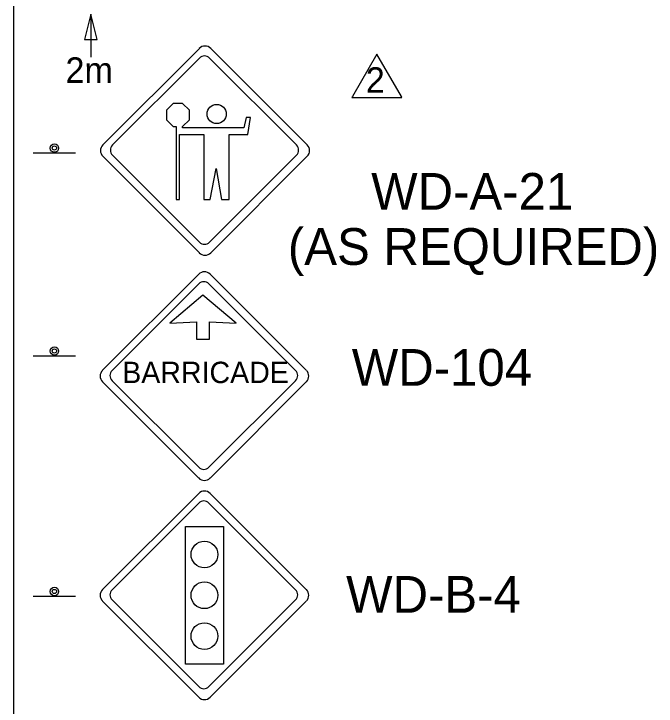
# Model space of a CAD drawing. Extents: x 2170 to 2386, y 134 to 413.
# Drawn here: x 2234.19 to 2270.72, y 251.29 to 290.65 of the extents above; entities that cross this region are included whole.
import ezdxf

# ---------------------------------------------------------------- set-up
doc = ezdxf.new("R2010")
doc.units = 0
for name, color, linetype in [('Level 1', 7, 'Continuous'), ('Level 10', 7, 'Continuous'), ('Level 44', 7, 'Continuous'), ('Level 60', 7, 'Continuous')]:
    doc.layers.add(name, color=color, linetype=linetype)

msp = doc.modelspace()

# ---------------------------------------------------------------- linework, layer by layer
at = {"layer": 'Level 1'}
for p, q in [((2243.249, 285.56), (2242.865, 285.176)), ((2243.791, 285.56), (2243.249, 285.56)), ((2244.175, 285.176), (2243.791, 285.56)), ((2242.865, 285.176), (2242.865, 284.634)), ((2244.175, 284.634), (2244.175, 285.176)), ((2242.865, 284.634), (2243.249, 284.25)), ((2243.791, 284.25), (2244.175, 284.634)), ((2247.407, 284.763), (2247.268, 284.18)), ((2247.651, 284.763), (2247.407, 284.763)), ((2247.492, 283.789), (2247.651, 284.763)), ((2243.249, 284.25), (2243.423, 284.25)), ((2243.423, 284.25), (2243.423, 280.097)), ((2243.791, 284.18), (2243.791, 284.25)), ((2247.268, 284.18), (2243.791, 284.18)), ((2243.613, 280.097), (2243.613, 283.789)), ((2243.613, 283.789), (2244.995, 283.789)), ((2244.995, 283.789), (2244.995, 280.097)), ((2246.445, 280.097), (2246.445, 283.789)), ((2246.445, 283.789), (2247.492, 283.789)), ((2245.362, 280.097), (2245.69, 281.866)), ((2245.69, 281.866), (2245.998, 280.097)), ((2243.423, 280.097), (2243.613, 280.097)), ((2244.995, 280.097), (2245.362, 280.097)), ((2245.998, 280.097), (2246.445, 280.097)), ((2243.949, 261.504), (2246.109, 261.504)), ((2243.949, 253.671), (2243.949, 261.504)), ((2243.949, 253.678), (2243.949, 261.504)), ((2246.109, 261.504), (2246.109, 253.678)), ((2246.109, 253.678), (2243.949, 253.678)), ((2243.949, 253.678), (2243.949, 253.671))]:
    msp.add_line(p, q, dxfattribs=at)
msp.add_circle((2245.725, 284.958), 0.544, dxfattribs=at)
at = {"layer": 'Level 10'}
for p, q in [((2234.191, 178.244), (2234.191, 321.298)), ((2238.57, 290.645), (2238.57, 288.196))]:
    msp.add_line(p, q, dxfattribs=at)
msp.add_lwpolyline([(2238.933, 289.194), (2238.57, 290.645), (2238.207, 289.194)], close=True, dxfattribs=at)
at = {"layer": 'Level 44'}
for p, q in [((2244.741, 288.689), (2239.247, 283.203)), ((2250.875, 283.203), (2245.39, 288.689)), ((2239.797, 283.199), (2244.741, 288.136)), ((2245.325, 288.136), (2250.263, 283.199)), ((2235.294, 282.754), (2237.69, 282.754)), ((2239.247, 282.552), (2244.741, 277.061)), ((2239.252, 282.552), (2239.247, 282.552)), ((2244.741, 277.672), (2239.797, 282.612)), ((2250.263, 282.612), (2245.325, 277.672)), ((2245.39, 277.061), (2250.875, 282.552)), ((2244.707, 275.853), (2239.229, 270.384)), ((2250.823, 270.384), (2245.354, 275.853)), ((2239.778, 270.379), (2244.707, 275.302)), ((2245.289, 275.302), (2250.213, 270.379)), ((2244.948, 274.656), (2243.066, 273.07)), ((2246.83, 273.07), (2244.948, 274.656)), ((2243.066, 273.07), (2244.571, 273.15)), ((2244.571, 273.15), (2244.571, 272.146)), ((2245.325, 272.146), (2245.325, 273.15)), ((2245.325, 273.15), (2246.83, 273.07)), ((2244.571, 272.146), (2245.32, 272.146)), ((2235.294, 271.214), (2237.69, 271.214)), ((2239.229, 269.734), (2244.707, 264.259)), ((2239.234, 269.734), (2239.229, 269.734)), ((2244.707, 264.868), (2239.778, 269.795)), ((2250.213, 269.795), (2245.289, 264.868)), ((2245.354, 264.259), (2250.823, 269.734)), ((2244.707, 263.385), (2239.229, 257.916)), ((2250.823, 257.916), (2245.354, 263.385)), ((2239.778, 257.911), (2244.707, 262.834)), ((2245.289, 262.834), (2250.213, 257.911)), ((2235.294, 257.542), (2237.69, 257.542)), ((2239.229, 257.266), (2244.707, 251.791)), ((2239.234, 257.266), (2239.229, 257.266)), ((2244.707, 252.4), (2239.778, 257.327)), ((2250.213, 257.327), (2245.289, 252.4)), ((2245.354, 251.791), (2250.823, 257.266))]:
    msp.add_line(p, q, dxfattribs=at)
for centre, radius in [((2236.497, 283.023), 0.24), ((2236.497, 283.023), 0.12), ((2236.497, 271.482), 0.24), ((2236.497, 271.482), 0.12), ((2245.029, 259.91), 0.76), ((2245.029, 257.591), 0.76), ((2236.497, 257.81), 0.24), ((2236.497, 257.81), 0.12), ((2245.029, 255.271), 0.76)]:
    msp.add_circle(centre, radius, dxfattribs=at)
for centre, radius, start, end in [((2245.064, 288.365), 0.459, 45, 135), ((2245.032, 287.844), 0.413, 45, 135), ((2239.576, 282.877), 0.459, 135, 225), ((2240.092, 282.905), 0.413, 135, 225), ((2249.971, 282.905), 0.413, 315, 45), ((2250.553, 282.877), 0.459, 315, 45), ((2245.032, 277.965), 0.413, 225, 315), ((2245.064, 277.389), 0.459, 225, 315), ((2245.029, 275.531), 0.458, 45, 135), ((2244.997, 275.012), 0.412, 45, 135), ((2239.557, 270.059), 0.458, 135, 225), ((2240.071, 270.086), 0.412, 135, 225), ((2249.922, 270.086), 0.412, 315, 45), ((2250.502, 270.059), 0.458, 315, 45), ((2244.997, 265.161), 0.412, 225, 315), ((2245.029, 264.586), 0.458, 225, 315), ((2245.029, 263.063), 0.458, 45, 135), ((2244.997, 262.544), 0.412, 45, 135), ((2239.557, 257.591), 0.458, 135, 225), ((2240.071, 257.618), 0.412, 135, 225), ((2249.922, 257.618), 0.412, 315, 45), ((2250.502, 257.591), 0.458, 315, 45), ((2244.997, 252.693), 0.412, 225, 315), ((2245.029, 252.118), 0.458, 225, 315)]:
    msp.add_arc(centre, radius, start, end, dxfattribs=at)
at = {"layer": 'Level 60'}
for points in [[(2254.835, 288.37), (2253.442, 285.945)], [(2256.228, 285.945), (2254.834, 288.37)], [(2253.442, 285.945), (2253.416, 285.9), (2256.255, 285.9), (2256.229, 285.945)]]:
    msp.add_lwpolyline(points, dxfattribs=at)

# ---------------------------------------------------------------- texts
at = {"layer": 'Level 10'}
for s, height, p in [('2m', 1.4514, (2237.128, 286.729)), ('WD-A-21', 2.09, (2254.514, 279.513)), ('(AS REQUIRED)', 2.09001, (2249.774, 276.379)), ('WD-104', 2.09, (2253.412, 269.502)), ('WD-B-4', 2.09, (2253.088, 256.596))]:
    msp.add_text(s, height=height, dxfattribs=at).set_placement(p)
at = {"layer": 'Level 44'}
msp.add_text('BARRICADE', height=1.2144, rotation=360, dxfattribs=at).set_placement((2240.355, 269.658))
at = {"layer": 'Level 60'}
msp.add_text('2', height=1.448, rotation=360, dxfattribs=at).set_placement((2254.208, 286.169))

doc.saveas('drawing.dxf')
